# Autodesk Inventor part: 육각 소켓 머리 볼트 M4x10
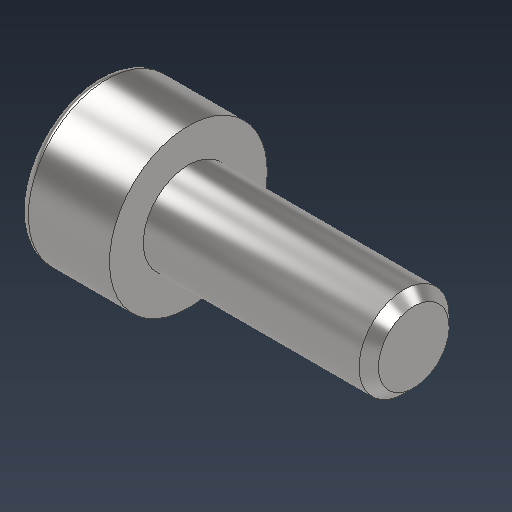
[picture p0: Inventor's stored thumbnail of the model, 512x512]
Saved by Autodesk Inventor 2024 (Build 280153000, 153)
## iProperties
Created: 2024-05
Part Number: 육각 소켓 머리 볼트 M4x10
Material: 강철, 연강
Description: 6각머리 태핑 나사
Document SubType Name: Modeling
Designer: kh_501
Density: 7.85 g/cm^3
Appearance: 기본값
Author: jhkim
Sending System: Autodesk Inventor 2025
Preprocessor: ST-DEVELOPER v20
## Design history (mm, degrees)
node "육각 소켓 머리 볼트 M4x101"
node "솔리드1"
body "Solid1"
